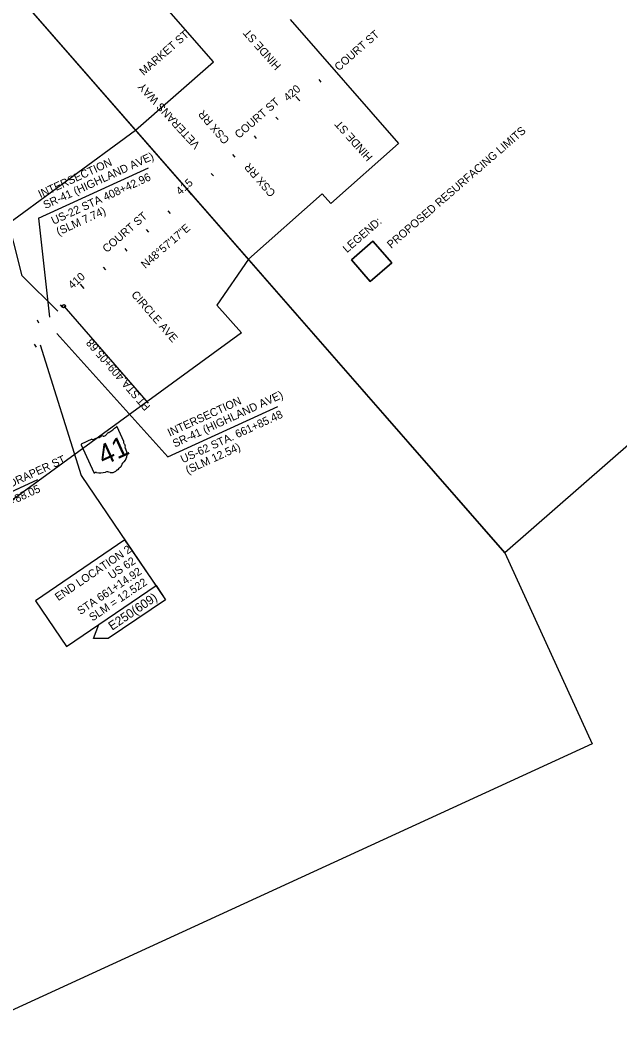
# Model space of a CAD drawing. Extents: x 127199 to 143299, y 479188 to 491521.
# Drawn here: x 137310 to 139409, y 482957 to 486473 of the extents above; entities that cross this region are included whole.
import ezdxf

# ---------------------------------------------------------------- set-up
doc = ezdxf.new("R2010")
doc.units = 0
for name, color, linetype in [('PM_P_CL_Double_Solid', 7, 'Continuous'), ('PM_P_Stop_Line', 7, 'Continuous'), ('PM_X_CL_Double_Solid', 7, 'Continuous'), ('PM_X_CL_Pass_Proh_Lt', 7, 'Continuous'), ('PM_X_Lane_Line', 7, 'Continuous'), ('PV_X_Parking_Lot', 7, 'Continuous'), ('PV_X_Walk', 7, 'Continuous'), ('RD_X_RR_2', 7, 'Continuous'), ('SH_Data', 7, 'Continuous')]:
    doc.layers.add(name, color=color, linetype=linetype)

msp = doc.modelspace()

# ---------------------------------------------------------------- linework, layer by layer
at = {"layer": 'PM_P_CL_Double_Solid'}
msp.add_lwpolyline([(138610.7, 485623.6), (138535.3, 485557.8), (138469.6, 485633.2), (138544.9, 485698.9)], close=True, dxfattribs=at)
at = {"layer": 'PM_P_Stop_Line'}
for p, q in [((137673, 484998.2), (137649.7, 485049)), ((137523.5, 484986.4), (137567.9, 484889.2)), ((137561.5, 485005.8), (137524, 484988.7)), ((137673, 484998.2), (137673, 484998.2))]:
    msp.add_line(p, q, dxfattribs=at)
for centre, radius, start, end in [((137544.7, 485158.3), 149.3, 300.3997, 313.4617), ((137648.2, 485048.6), 1.57, 16.4173, 122.2932), ((137565.3, 485021.2), 15.8, 256.1747, 295.6671), ((137600.2, 484957.5), 56.8, 105.0419, 119.5435), ((137587.4, 485016.5), 4.57, 244.3473, 321.6576), ((137598.6, 485008), 9.49, 79.0219, 143.6964), ((137602.7, 485028.5), 11.4, 258.4114, 319.3834), ((137636.1, 485004), 30, 121.9014, 145.3241), ((137524.9, 484987.3), 1.63, 122.6853, 212.6853), ((137674.4, 484994.3), 2.43, 132.4992, 234.8922), ((137671.6, 484997.3), 1.68, 314.159, 32.2894), ((137663.3, 484981.4), 14.6, 4.5882, 48.2048), ((137647.6, 484953.1), 37.4, 316.8641, 33.5411), ((137687.8, 484979.2), 10.6, 161.3617, 211.4848), ((137646.7, 484909), 11.4, 293.3323, 340.1045), ((137660.4, 484903.9), 3.21, 90.307, 157.2037), ((137653.1, 484916.7), 12.1, 307.4284, 347.8323), ((137684.8, 484909.6), 20.5, 118.9584, 167.132), ((137569.5, 484889.7), 1.65, 196.5136, 282.8619), ((137565.2, 484899.7), 12.6, 291.8942, 305.1591), ((137574.5, 484885.4), 4.53, 54.3036, 117.827), ((137586.7, 484996.6), 107.8, 264.9682, 281.7537), ((137614.7, 484857.8), 33.7, 71.7394, 100.3912), ((137630.7, 484910.5), 21.4, 255.2556, 310.8471), ((137657.3, 484882.1), 17.6, 110.2504, 135.7652)]:
    msp.add_arc(centre, radius, start, end, dxfattribs=at)
at = {"layer": 'PM_X_CL_Double_Solid'}
msp.add_line((137463.5, 485471.3), (137758.9, 485131.9), dxfattribs=at)
msp.add_circle((137463.5, 485471.3), 6, dxfattribs=at)
at = {"layer": 'PM_X_Lane_Line'}
for p, q in [((137317.8, 485578.2), (137109.2, 486393.9)), ((137375.1, 485779.2), (137759.2, 485955.4)), ((137375.1, 485779.2), (137413.4, 485433.5)), ((137442.7, 485454.3), (137317.8, 485578.2)), ((137438.3, 485376.3), (137827.6, 484944.6)), ((137379.9, 485336.6), (137524.4, 484878.8)), ((137827.6, 484944.6), (138211.7, 485120.8)), ((137524.4, 484878.8), (137819.3, 484444.5)), ((136988.5, 484688.6), (137372.6, 484864.7)), ((137585.4, 484357.6), (137785.9, 484493.8)), ((137785.9, 484493.8), (137819.3, 484444.5)), ((137819.3, 484444.5), (137618.8, 484308.4)), ((137566.9, 484309.1), (137585.4, 484357.6)), ((137618.8, 484308.4), (137566.9, 484309.1))]:
    msp.add_line(p, q, dxfattribs=at)
msp.add_lwpolyline([(137677.2, 484653.8), (137363.6, 484440.9), (137472.3, 484280.9), (137785.9, 484493.8)], close=True, dxfattribs=at)
at = {"layer": 'PV_X_Walk'}
for p, q in [((138364.2, 486255.5), (138356.3, 486264.6)), ((138288.8, 486189.9), (138275.6, 486205)), ((138213.4, 486124.2), (138205.5, 486133.3)), ((138137.9, 486058.5), (138130.1, 486067.6)), ((138062.5, 485992.9), (138054.6, 486001.9)), ((137987.1, 485927.2), (137979.2, 485936.3)), ((137911.7, 485861.5), (137898.5, 485876.6)), ((137836.3, 485795.9), (137828.4, 485804.9)), ((137760.8, 485730.2), (137753, 485739.3)), ((137685.4, 485664.6), (137677.5, 485673.6)), ((137610, 485598.9), (137602.1, 485607.9)), ((137534.6, 485533.2), (137521.5, 485548.3)), ((137459.1, 485467.6), (137451.4, 485476.7)), ((137376.3, 485411.9), (137370.8, 485422.5)), ((137367.5, 485328.3), (137360.8, 485338.2))]:
    msp.add_line(p, q, dxfattribs=at)
at = {"layer": 'RD_X_RR_2'}
for p, q in [((136629.2, 487330.1), (139006.1, 484608.4)), ((137987.5, 486326.2), (137766.9, 486578.7)), ((138255.8, 486474.9), (138634.2, 486040.3)), ((137714.3, 486087.5), (137987.5, 486326.2)), ((137151.7, 485674.5), (137714.3, 486087.5)), ((138634.2, 486040.3), (138397.9, 485830.4)), ((138367, 485865.2), (138109, 485635.6)), ((138397.9, 485830.4), (138367, 485865.2)), ((138109, 485635.6), (137998.2, 485475.2)), ((137998.2, 485475.2), (138084.8, 485377.8)), ((138084.8, 485377.8), (137274.6, 484786.8)), ((139006.1, 484608.4), (139312.6, 483940)), ((139312.6, 483940), (134131.4, 481564))]:
    msp.add_line(p, q, dxfattribs=at)
msp.add_lwpolyline([(136243.4, 487771.9), (140536.7, 491521.2), (143299.3, 488357.8), (139006.1, 484608.4)], close=True, dxfattribs=at)
at = {"layer": 'SH_Data'}
msp.add_lwpolyline([(138544.9, 485698.9), (138469.6, 485633.2), (138535.3, 485557.8), (138610.7, 485623.6)], close=True, dxfattribs=at)

# ---------------------------------------------------------------- texts
at = {"layer": 'PM_P_Stop_Line'}
msp.add_text('41', height=70.41, rotation=24.5552, dxfattribs=at).set_placement((137602.3, 484913.2))
at = {"layer": 'PM_X_CL_Double_Solid'}
for s, p in [('409+05.68', (137676.7, 485225.7)), (' STA. ', (137738.8, 485154.4)), ('PT', (137767.8, 485121.1))]:
    msp.add_text(s, height=28, rotation=131.0453, dxfattribs=at).set_placement(p)
at = {"layer": 'PM_X_CL_Pass_Proh_Lt'}
for s, p in [('PROPOSED RESURFACING LIMITS', (138609, 485671.7)), ('LEGEND:', (138454.1, 485656.7))]:
    msp.add_text(s, height=28, rotation=40.8854, dxfattribs=at).set_placement(p)
at = {"layer": 'PM_X_Lane_Line'}
for s, height, rotation, p in [('MARKET ST', 28, 41.131, (137742.4, 486277.1)), ('HINDE ST', 28, 131.6235, (138225.6, 486313.4)), ('COURT ST', 28, 41.0453, (138425.4, 486293)), ('VETERANS WAY', 28, 132.5663, (137942, 486037.2)), ('COURT ST', 28, 41.0453, (138076.1, 486056.4)), ('CSX RR', 28, 131.0938, (138044.8, 486053.7)), ('HINDE ST', 28, 131.6235, (138546, 485994.2)), ('SR-41 (HIGHLAND AVE)', 28, 24.6363, (137398.9, 485811.2)), ('INTERSECTION', 28, 24.6363, (137381.4, 485849.3)), ('CSX RR', 28, 131.0938, (138206.3, 485868.8)), ('US-22 STA 408+42.96', 28, 24.6363, (137427.2, 485756.2)), ('(SLM 7.74)', 28, 24.6363, (137444.7, 485718)), ('COURT ST', 28, 41.0453, (137613.4, 485656.9)), ('CIRCLE AVE', 28, 311.0453, (137697.4, 485510.5)), ('INTERSECTION', 28, 24.6363, (137833.9, 485014.7)), ('SR-41 (HIGHLAND AVE)', 28, 24.6363, (137851.4, 484976.6)), ('US-62 STA. 661+85.48', 28, 24.6363, (137879.6, 484921.6)), ('(SLM 12.54)', 28, 24.6363, (137897.1, 484883.4)), ('INTERSECTION DRAPER ST', 28, 24.6363, (137014.4, 484715.9)), ('US-62 STA 654+88.05', 28, 24.6363, (137040.5, 484665.5)), ('END LOCATION 2', 28, 34.0425, (137443.8, 484439.2)), ('US 62', 28, 34.0425, (137630.8, 484514.8)), ('STA 661+14.92', 28, 34.0425, (137521.7, 484390.4)), ('SLM = 12.522', 28, 34.0425, (137563.4, 484367.9)), ('E250(609)', 31.2, 34.0425, (137632.2, 484335.8))]:
    msp.add_text(s, height=height, rotation=rotation, dxfattribs=at).set_placement(p)
at = {"layer": 'PV_X_Parking_Lot'}
msp.add_text('N48°57\'17"E', height=28, rotation=41.0453, dxfattribs=at).set_placement((137748.2, 485601.7))
at = {"layer": 'PV_X_Walk'}
for s, p in [('420', (138247.1, 486186.8)), ('415', (137870.3, 485858.7)), ('410', (137492.9, 485530.1))]:
    msp.add_text(s, height=28, rotation=41.0453, dxfattribs=at).set_placement(p)

doc.saveas('drawing.dxf')
